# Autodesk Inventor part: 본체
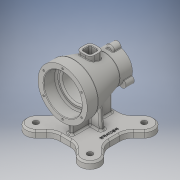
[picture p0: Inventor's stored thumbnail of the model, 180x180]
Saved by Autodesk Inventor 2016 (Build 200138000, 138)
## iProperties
Created: 2018-03
Part Number: 본체
Material: 일반
Document SubType Name: Modeling
Designer: USER
Density: 1 g/cm^3
Appearance: 기본값
Author: USER
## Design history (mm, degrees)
sketch "스케치1"
  geometry: L1 (0, 50)-(0, -50); L2 (36, 50)-(45, 50); L3 (45, 50)-(45, 30.45); L4 (44.868, 29.57)-(27.632, -26.57); L5 (27.5, -27.45)-(27.5, -50); L6 (27.5, -50)-(21, -50); L7 (35, 49)-(35, 30); L8 (32, 27)-(29, 27); L9 (26, 24)-(26, -17); L10 (23, -20)-(23, -20); L11 (20, -23)-(20, -49); L12 (36, 50)-(35, 49); L13 (20, -49)-(21, -50); A1 r 3 centre (32, 30) between (32, 27) and (35, 30); A2 r 3 centre (29, 24) between (29, 27) and (26, 24); A3 r 3 centre (23, -17) between (23, -20) and (26, -17); A4 r 3 centre (42, 30.45) between (44.868, 29.57) and (45, 30.45); A5 r 3 centre (30.5, -27.45) between (27.632, -26.57) and (27.5, -27.45); A6 r 3 centre (23, -23) between (23, -20) and (20, -23); 9 further points
  constraints: 26 end point, 14 point on line, 12 point on circle, 12 tangent, 6 centre point, 5 perpendicular, 4 equal radius, 2 horizontal alignment, 2 vertical, 1 coincident, 1 horizontal, 1 midpoint, 1 parallel
  dimensions: "d0" = 100 distance of L1.start L1.end; "d1" = 70 diameter of L7 L1; "d2" = 52 diameter of L9 L1; "d3" = 40 diameter of L11 L1; "d4" = 90 diameter of L3 L1; "d5" = 55 diameter of L5 L1; "d6" = 77 distance from line of point (27.5, -27) L2; "d7" = 20 distance of L2.end point (45, 30); "d8" = 23 distance of point (35, 50) point (35, 27); "d9" = 47 distance of point (26, 27) point (26, -20); "d10" = 3 radius of A1; "d11" = 1 distance of L2.start point (35, 50); "d12" = 1 distance of L7.start point (35, 50) (= d11); "d13" = 1 distance of L11.end point (20, -50) (= d11); "d14" = 1 distance of L6.end point (20, -50) (= d13); "d15" = 3 radius of A6
revolve "회전1" sketch "스케치1" stored, may be unused: angle "d16" = 90 deg
sketch "스케치2"
  geometry: A1 r 27.5 centre (0, 0) between (0, 27.5) and (-6.943, 26.609) reference; A2 r 7 centre (0, 27.5) between (6.943, 26.609) and (-6.943, 26.609); 1 further point
  constraints: 5 point on circle, 1 centre point, 1 vertical alignment
  dimensions: "d17" = 7 radius of A2
extrude "돌출1" join sketch "스케치2" distance "d18" = 15; taper "d19" = 0 deg
sketch "스케치3"
  geometry: A1 r 7 centre (0, 0) between (6.943, -0.891) and (-6.943, -0.891) reference; 2 further points
  constraints: 1 coincident
hole "구멍1" sketch "스케치3" at (0, 0) diameter "d20" = 3.242; stored, may be unused: countersink angle "d24" = 90 deg, drill point angle "d26" = 118 deg; dims "d21" = 9, "d22" = 4, "d23" = 2, "d25" = 11
fillet "모깎기1" dims "d30" = 1
node "작업 평면1"
sketch "스케치4"
  geometry: L1 (-45, 45)-(45, 45); L2 (45, 45)-(45, -45); L3 (45, -45)-(-45, -45); L4 (-45, -45)-(-45, 45); L5 (-45, 45)-(45, -45); L6 (52.616, 52.616)-(-45, -45); 2 further points
  constraints: 12 end point, 2 parallel, 2 perpendicular, 2 point on line, 1 coincident, 1 horizontal, 1 midpoint, 3 other
  dimensions: "d32" = 90 distance of L1.end L2.end
extrude "돌출2" join sketch "스케치4" distance "d33" = 12; taper "d34" = 0 deg
sketch "스케치6"
  geometry: L1 (45, -45)-(45, 45) reference; L2 (-45, 45)-(45, 45) reference; L3 (-49.497, -49.497)-(49.497, 49.497); L4 (36.77, 62.225)-(19.544, 45); L5 (62.225, 36.77)-(45, 19.544); L6 (45, -45)-(-45, -45) reference; L7 (-45, -45)-(-45, 45) reference; L8 (-49.497, 49.497)-(49.497, -49.497); L9 (62.225, -36.77)-(45, -19.544); L10 (-36.77, -62.225)-(-19.544, -45); L11 (-62.225, 36.77)-(-45, 19.544); L12 (-36.77, 62.225)-(-19.544, 45); L13 (36.77, -62.225)-(19.544, -45); L14 (-62.225, -36.77)-(-45, -19.544); C1 r 5 at (49.497, 49.497); C2 r 5 at (49.497, -49.497); C3 r 5 at (-49.497, -49.497); C4 r 5 at (-49.497, 49.497); A1 r 70 centre (0, 0) between (49.497, 49.497) and (-49.497, -49.497); A2 r 18 centre (49.497, 49.497) between (62.225, 36.77) and (36.77, 62.225); A3 r 18 centre (49.497, -49.497) between (36.77, -62.225) and (62.225, -36.77); A4 r 18 centre (-49.497, -49.497) between (-62.225, -36.77) and (-36.77, -62.225); A5 r 18 centre (-49.497, 49.497) between (-36.77, 62.225) and (-62.225, 36.77); 1 further point
  constraints: 20 end point, 12 point on circle, 9 centre point, 9 coincident, 8 parallel, 8 point on line, 8 tangent, 6 equal radius, 2 midpoint
  dimensions: "d35" = 140 diameter of A1; "d36" = 45 deg angle of L3 L2; "d37" = 10 diameter of C1; "d38" = 18 radius of A2; "d39" = 45 deg angle of L8 L6
extrude "돌출3" join sketch "스케치6" distance "d40" = 12; taper "d41" = 0 deg
fillet "모깎기2" dims "d42" = 25
chamfer "모따기1" distance "d43" = 3; stored, may be unused: second distance "d44" = 2, angle "d45" = 45 deg
sketch "스케치7"
  geometry: L1 (4, -37)-(-4, -37); L2 (-4, -37)-(-4, 37); L3 (-4, 37)-(4, 37); L4 (4, 37)-(4, -37); L5 (4, -37)-(-4, 37); L6 (-4, -37)-(4, 37); 2 further points
  constraints: 12 end point, 4 midpoint, 2 parallel, 1 horizontal, 1 perpendicular
  dimensions: "d46" = 8 distance between parallel lines of L4 L2; "d47" = 37 vertical distance of L1.end point (0, 0)
extrude "돌출4" join sketch "스케치7" stored distance "d48" = 12; taper "d49" = 0 deg
sketch "스케치8"
  geometry: L1 (-4, -70)-(4, -70) reference; L2 (4, -70)-(-4, -70) reference; L3 (44.497, -70)-(54.497, -70) reference; L4 (-54.497, -70)-(-44.497, -70) reference; L5 (-54.497, -70)-(-44.497, -70) reference; L6 (44.497, -70)-(54.497, -70) reference; L7 (50.201, -70)-(42, -70) reference; L8 (60.104, -70)-(50.201, -70) reference; L9 (38.891, -70)-(60.104, -70) reference; L10 (28.988, -70)-(38.891, -70) reference; L11 (9.189, -70)-(28.988, -70) reference; L12 (-9.189, -70)-(9.189, -70) reference; L13 (-28.988, -70)-(-9.189, -70) reference; L14 (-38.891, -70)-(-28.988, -70) reference; L15 (-60.104, -70)-(-38.891, -70) reference; L16 (-50.201, -70)-(-60.104, -70) reference; L17 (-42, -70)-(-50.201, -70) reference; L18 (-50.201, -70)-(-42, -70) reference; L19 (-60.104, -70)-(-50.201, -70) reference; L20 (-38.891, -70)-(-60.104, -70) reference; L21 (-28.988, -70)-(-38.891, -70) reference; L22 (-9.189, -70)-(-28.988, -70) reference; L23 (9.189, -70)-(-9.189, -70) reference; L24 (28.988, -70)-(9.189, -70) reference; L25 (38.891, -70)-(28.988, -70) reference; L26 (60.104, -70)-(38.891, -70) reference; L27 (50.201, -70)-(60.104, -70) reference; L28 (42, -70)-(50.201, -70) reference; L29 (-38.891, -70)-(-28.988, -70) reference; L30 (-24, -70)-(-21.979, -46.903); L31 (28.988, -70)-(38.891, -70) reference; L32 (24, -70)-(22.037, -47.558); 1 further point
  constraints: 4 end point, 2 point on line
  dimensions: "d50" = 24 horizontal distance of L30.start point (0, 0); "d51" = 24 horizontal distance of L32.start point (0, 0); "d52" = 95 deg angle of L30 L21; "d53" = 95 deg angle of L32 L25
  node "투영된 루프1"
feature "리브1" dims "d54" = 1, "d55" = 8, "d56" = 0, "d57" = 0, "d58" = 1, "d59" = 1
feature "리브2" dims "d60" = 1, "d61" = 8, "d62" = 0, "d63" = 0, "d64" = 1, "d65" = 1
fillet "모깎기3" dims "d66" = 3
fillet "모깎기4" dims "d67" = 3
sketch "스케치9"
  geometry: 2 further points
  constraints: 1 horizontal alignment, 1 other
  dimensions: "d68" = 35 distance of point (35, 0) point (0, 0)
feature "엠보싱1" sketch "스케치9" dims "d0" = 100, "d1" = 70, "d2" = 52, "d3" = 40, "d4" = 90, "d5" = 55, "d6" = 77, "d7" = 20, "d8" = 23, "d9" = 47, "d10" = 3, "d11" = 1, "d12" = 1 (= d11), "d13" = 1 (= d11), "d14" = 1 (= d13), "d15" = 3, "d69" = 0.5, "d70" = 0
sketch "스케치10" dims "d71" = 80
  geometry: 3 further points
  constraints: 2 vertical alignment, 1 coincident, 2 other
hole "구멍2" sketch "스케치10" at (0, 40) diameter "d72" = 3.242; stored, may be unused: countersink angle "d76" = 90 deg, drill point angle "d78" = 118 deg; dims "d73" = 9, "d74" = 4, "d75" = 2, "d77" = 11
node "작업 평면2"
sketch "스케치11"
  geometry: L1 (-12.5, 12.5)-(12.5, 12.5); L2 (12.5, 12.5)-(12.5, -12.5); L3 (12.5, -12.5)-(-12.5, -12.5); L4 (-12.5, -12.5)-(-12.5, 12.5); L5 (-12.5, 12.5)-(12.5, -12.5); L6 (12.5, 12.5)-(-12.5, -12.5); 1 further point
  constraints: 12 end point, 2 midpoint, 2 parallel, 2 perpendicular, 1 horizontal
  dimensions: "d83" = 25 distance of L1.end L2.end
extrude "돌출5" join sketch "스케치11" stored distance "d84" = 12; taper "d85" = 0 deg
fillet "모깎기5" dims "d86" = 8
sketch "스케치12"
  geometry: L1 (-4.5, -7.5)-(4.5, -7.5); L2 (7.5, -4.5)-(7.5, 4.5); L3 (4.5, 7.5)-(-4.5, 7.5); L4 (-7.5, 4.5)-(-7.5, -4.5); L5 (-7.5, -7.5)-(7.5, 7.5); L6 (7.5, -7.5)-(-7.5, 7.5); A1 r 3 centre (-4.5, -4.5) between (-7.5, -4.5) and (-4.5, -7.5); A2 r 3 centre (4.5, -4.5) between (4.5, -7.5) and (7.5, -4.5); A3 r 3 centre (4.5, 4.5) between (7.5, 4.5) and (4.5, 7.5); A4 r 3 centre (-4.5, 4.5) between (-4.5, 7.5) and (-7.5, 4.5); 1 further point
  constraints: 12 end point, 8 point on circle, 8 point on line, 8 tangent, 4 centre point, 3 equal radius, 2 midpoint, 2 parallel, 2 perpendicular, 1 horizontal
  dimensions: "d87" = 15 distance of L6.end L5.start; "d88" = 3 radius of A1
extrude "돌출6" cut sketch "스케치12" distance "d89" = 30; taper "d90" = 0 deg
fillet "모깎기6" dims "d91" = 1
chamfer "모따기2" distance "d92" = 1; stored, may be unused: second distance "d93" = 2, angle "d94" = 45 deg
fillet "모깎기7" dims "d95" = 3
fillet "모깎기8" dims "d96" = 1
node "솔리드1"
pattern_circular "원형 패턴1" dims angle "d28" = 360 deg
pattern_circular "원형 패턴2" dims angle "d80" = 360 deg
other parameters: "d31" = -82, "d82" = 45
